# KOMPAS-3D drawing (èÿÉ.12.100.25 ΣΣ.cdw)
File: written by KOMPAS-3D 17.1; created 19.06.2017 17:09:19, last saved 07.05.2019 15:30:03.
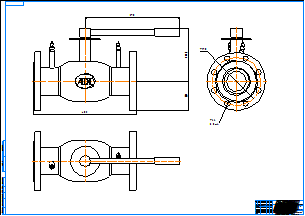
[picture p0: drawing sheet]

Sheet 1: A0, landscape

Title block, sheet 1: name: КШР.12.100.25 фф; material: Внимание! Данный продукт является объектом авторского права ООО «Торговый Дом АДЛ». / Запрещается изменение, копирование, распространение / (в том числе путем копирования на другие сайты и ресурсы в Интернете) / или любое иное использование информации и объектов без предварительного / согласия правообладателя (ООО «Торговый Дом АДЛ»).; scale: 1:1; sheets: 1; organisation: ООО "Торговый дом АДЛ"; sheet format: A0; stored path: C:\Users\tra\Desktop\2д чертежи\Шаровые краны БИВАЛ\КШР_Бивал_серия_12\KOMPAS 2D\КШР.12.100.25 фф.cdw

Views: Спереди 1, Проекционный вид 2, Проекционный вид 3
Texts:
  Klimkovich
  ADL
Dimensions and other numbers on the sheet: 405; 370; 205,1; 115; 190; 22; 8 Отв.; 1:1; 1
